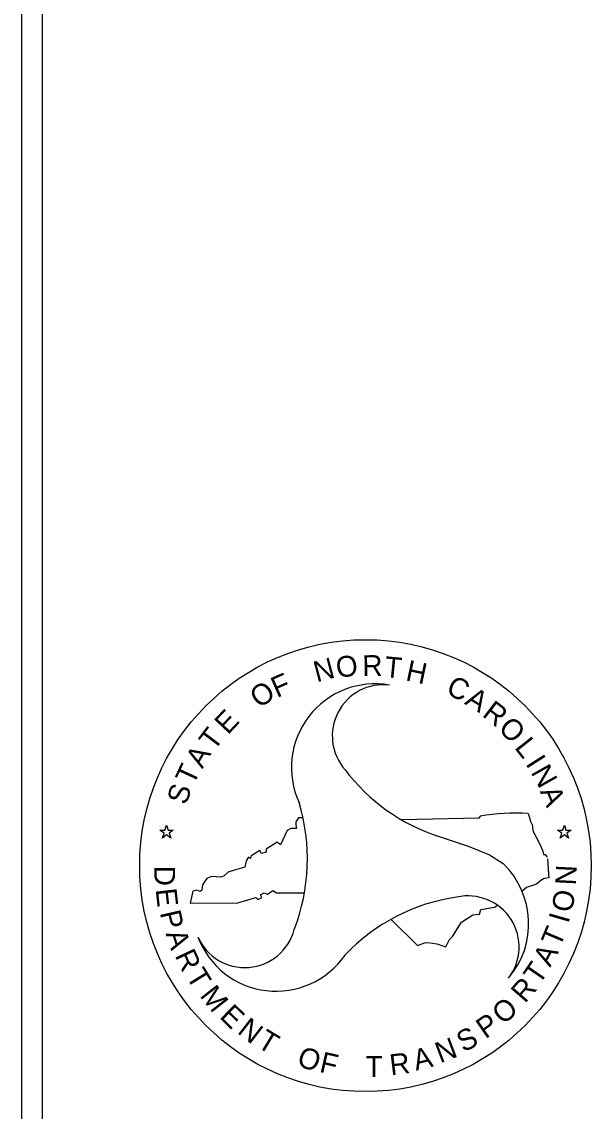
# Model space of a CAD drawing. Extents: x 2598976 to 2600165, y 728604 to 730243.
# Drawn here: x 2598980.7 to 2599099.3, y 728825.9 to 729052.5 of the extents above; entities that cross this region are included whole.
import ezdxf

# ---------------------------------------------------------------- set-up
doc = ezdxf.new("R2010")
doc.units = 0
doc.layers.add('Old_Level_63', color=7, linetype='Continuous')

msp = doc.modelspace()

# ---------------------------------------------------------------- linework, layer by layer
at = {"layer": 'Old_Level_63'}
for p, q in [((2598980.71, 728675.66), (2598980.71, 730208.07)), ((2598980.71, 728675.66), (2598980.71, 730208.07)), ((2598980.71, 728675.66), (2598980.71, 730208.07)), ((2598985.01, 728674.53), (2598985.01, 730208.54)), ((2598985.01, 728674.53), (2598985.01, 730208.54)), ((2598985.01, 728674.53), (2598985.01, 730208.54)), ((2599038.31, 728886.96), (2599037.8, 728886.13)), ((2599038.31, 728886.96), (2599037.8, 728886.13)), ((2599038.31, 728886.96), (2599037.8, 728886.13)), ((2599039.27, 728886.94), (2599038.31, 728886.96)), ((2599039.27, 728886.94), (2599038.31, 728886.96)), ((2599039.27, 728886.94), (2599038.31, 728886.96)), ((2599075.88, 728886.84), (2599059.86, 728886.48)), ((2599075.88, 728886.84), (2599059.86, 728886.48)), ((2599075.88, 728886.84), (2599059.86, 728886.48)), ((2599076.16, 728887.28), (2599075.88, 728886.84)), ((2599076.16, 728887.28), (2599075.88, 728886.84)), ((2599076.16, 728887.28), (2599075.88, 728886.84)), ((2599086.15, 728887.82), (2599086.42, 728886.98)), ((2599086.15, 728887.82), (2599086.42, 728886.98)), ((2599086.15, 728887.82), (2599086.42, 728886.98)), ((2599086.42, 728886.98), (2599086.49, 728886.62)), ((2599086.42, 728886.98), (2599086.49, 728886.62)), ((2599086.42, 728886.98), (2599086.49, 728886.62)), ((2599086.49, 728886.62), (2599086.71, 728886.05)), ((2599086.49, 728886.62), (2599086.71, 728886.05)), ((2599086.49, 728886.62), (2599086.71, 728886.05)), ((2599010.33, 728883.74), (2599009.47, 728884.37)), ((2599009.47, 728884.37), (2599010.53, 728884.37)), ((2599010.33, 728883.74), (2599009.47, 728884.37)), ((2599009.47, 728884.37), (2599010.53, 728884.37)), ((2599010.33, 728883.74), (2599009.47, 728884.37)), ((2599009.47, 728884.37), (2599010.53, 728884.37)), ((2599010.53, 728884.37), (2599010.86, 728885.38)), ((2599010.53, 728884.37), (2599010.86, 728885.38)), ((2599010.53, 728884.37), (2599010.86, 728885.38)), ((2599010.86, 728885.38), (2599011.18, 728884.37)), ((2599010.86, 728885.38), (2599011.18, 728884.37)), ((2599010.86, 728885.38), (2599011.18, 728884.37)), ((2599011.18, 728884.37), (2599012.25, 728884.37)), ((2599011.18, 728884.37), (2599012.25, 728884.37)), ((2599011.18, 728884.37), (2599012.25, 728884.37)), ((2599012.25, 728884.37), (2599011.39, 728883.74)), ((2599012.25, 728884.37), (2599011.39, 728883.74)), ((2599012.25, 728884.37), (2599011.39, 728883.74)), ((2599036.76, 728884.71), (2599035.98, 728884.31)), ((2599036.76, 728884.71), (2599035.98, 728884.31)), ((2599036.76, 728884.71), (2599035.98, 728884.31)), ((2599037.93, 728884.71), (2599036.76, 728884.71)), ((2599037.93, 728884.71), (2599036.76, 728884.71)), ((2599037.93, 728884.71), (2599036.76, 728884.71)), ((2599037.8, 728886.13), (2599037.8, 728885.48)), ((2599037.8, 728886.13), (2599037.8, 728885.48)), ((2599037.8, 728886.13), (2599037.8, 728885.48)), ((2599037.8, 728885.48), (2599037.93, 728884.71)), ((2599037.8, 728885.48), (2599037.93, 728884.71)), ((2599037.8, 728885.48), (2599037.93, 728884.71)), ((2599086.71, 728886.05), (2599087.06, 728885.34)), ((2599086.71, 728886.05), (2599087.06, 728885.34)), ((2599086.71, 728886.05), (2599087.06, 728885.34)), ((2599087.06, 728885.34), (2599087.06, 728884.84)), ((2599087.06, 728885.34), (2599087.06, 728884.84)), ((2599087.06, 728885.34), (2599087.06, 728884.84)), ((2599087.06, 728884.84), (2599087.21, 728883.99)), ((2599087.06, 728884.84), (2599087.21, 728883.99)), ((2599087.06, 728884.84), (2599087.21, 728883.99)), ((2599093.16, 728883.74), (2599092.3, 728884.37)), ((2599092.3, 728884.37), (2599093.36, 728884.37)), ((2599093.16, 728883.74), (2599092.3, 728884.37)), ((2599092.3, 728884.37), (2599093.36, 728884.37)), ((2599093.16, 728883.74), (2599092.3, 728884.37)), ((2599092.3, 728884.37), (2599093.36, 728884.37)), ((2599093.36, 728884.37), (2599093.69, 728885.38)), ((2599093.36, 728884.37), (2599093.69, 728885.38)), ((2599093.36, 728884.37), (2599093.69, 728885.38)), ((2599093.69, 728885.38), (2599094.02, 728884.37)), ((2599093.69, 728885.38), (2599094.02, 728884.37)), ((2599093.69, 728885.38), (2599094.02, 728884.37)), ((2599094.02, 728884.37), (2599095.08, 728884.37)), ((2599094.02, 728884.37), (2599095.08, 728884.37)), ((2599094.02, 728884.37), (2599095.08, 728884.37)), ((2599095.08, 728884.37), (2599094.22, 728883.74)), ((2599095.08, 728884.37), (2599094.22, 728883.74)), ((2599095.08, 728884.37), (2599094.22, 728883.74)), ((2599010, 728882.73), (2599010.33, 728883.74)), ((2599010, 728882.73), (2599010.33, 728883.74)), ((2599010, 728882.73), (2599010.33, 728883.74)), ((2599010.86, 728883.36), (2599010, 728882.73)), ((2599010.86, 728883.36), (2599010, 728882.73)), ((2599010.86, 728883.36), (2599010, 728882.73)), ((2599011.72, 728882.73), (2599010.86, 728883.36)), ((2599011.72, 728882.73), (2599010.86, 728883.36)), ((2599011.72, 728882.73), (2599010.86, 728883.36)), ((2599011.39, 728883.74), (2599011.72, 728882.73)), ((2599011.39, 728883.74), (2599011.72, 728882.73)), ((2599011.39, 728883.74), (2599011.72, 728882.73)), ((2599035.98, 728884.31), (2599034.56, 728881.33)), ((2599035.98, 728884.31), (2599034.56, 728881.33)), ((2599035.98, 728884.31), (2599034.56, 728881.33)), ((2599067.64, 728883.03), (2599073.67, 728881.04)), ((2599067.64, 728883.03), (2599073.67, 728881.04)), ((2599067.64, 728883.03), (2599073.67, 728881.04)), ((2599087.21, 728883.99), (2599087.56, 728883.48)), ((2599087.21, 728883.99), (2599087.56, 728883.48)), ((2599087.21, 728883.99), (2599087.56, 728883.48)), ((2599087.56, 728883.48), (2599087.85, 728882.92)), ((2599087.56, 728883.48), (2599087.85, 728882.92)), ((2599087.56, 728883.48), (2599087.85, 728882.92)), ((2599087.85, 728882.92), (2599088.56, 728881.42)), ((2599087.85, 728882.92), (2599088.56, 728881.42)), ((2599087.85, 728882.92), (2599088.56, 728881.42)), ((2599092.83, 728882.73), (2599093.16, 728883.74)), ((2599092.83, 728882.73), (2599093.16, 728883.74)), ((2599092.83, 728882.73), (2599093.16, 728883.74)), ((2599093.69, 728883.36), (2599092.83, 728882.73)), ((2599093.69, 728883.36), (2599092.83, 728882.73)), ((2599093.69, 728883.36), (2599092.83, 728882.73)), ((2599094.55, 728882.73), (2599093.69, 728883.36)), ((2599094.55, 728882.73), (2599093.69, 728883.36)), ((2599094.55, 728882.73), (2599093.69, 728883.36)), ((2599094.22, 728883.74), (2599094.55, 728882.73)), ((2599094.22, 728883.74), (2599094.55, 728882.73)), ((2599094.22, 728883.74), (2599094.55, 728882.73)), ((2599030.28, 728880.16), (2599028.46, 728878.99)), ((2599030.28, 728880.16), (2599028.46, 728878.99)), ((2599030.28, 728880.16), (2599028.46, 728878.99)), ((2599030.54, 728879.52), (2599030.28, 728880.16)), ((2599030.54, 728879.52), (2599030.28, 728880.16)), ((2599030.54, 728879.52), (2599030.28, 728880.16)), ((2599033.91, 728881.85), (2599031.57, 728880.42)), ((2599033.91, 728881.85), (2599031.57, 728880.42)), ((2599033.91, 728881.85), (2599031.57, 728880.42)), ((2599031.57, 728880.42), (2599031.57, 728879.77)), ((2599031.57, 728880.42), (2599031.57, 728879.77)), ((2599031.57, 728880.42), (2599031.57, 728879.77)), ((2599034.56, 728881.33), (2599033.91, 728881.85)), ((2599034.56, 728881.33), (2599033.91, 728881.85)), ((2599034.56, 728881.33), (2599033.91, 728881.85)), ((2599073.67, 728881.04), (2599078.11, 728879.23)), ((2599073.67, 728881.04), (2599078.11, 728879.23)), ((2599073.67, 728881.04), (2599078.11, 728879.23)), ((2599088.56, 728881.42), (2599089.2, 728879.99)), ((2599088.56, 728881.42), (2599089.2, 728879.99)), ((2599088.56, 728881.42), (2599089.2, 728879.99)), ((2599089.2, 728879.99), (2599089.34, 728879.28)), ((2599089.2, 728879.99), (2599089.34, 728879.28)), ((2599089.2, 728879.99), (2599089.34, 728879.28)), ((2599027.42, 728877.96), (2599027.16, 728876.66)), ((2599027.42, 728877.96), (2599027.16, 728876.66)), ((2599027.42, 728877.96), (2599027.16, 728876.66)), ((2599027.94, 728878.73), (2599027.42, 728877.96)), ((2599027.94, 728878.73), (2599027.42, 728877.96)), ((2599027.94, 728878.73), (2599027.42, 728877.96)), ((2599028.33, 728878.48), (2599027.94, 728878.73)), ((2599028.33, 728878.48), (2599027.94, 728878.73)), ((2599028.33, 728878.48), (2599027.94, 728878.73)), ((2599028.46, 728878.99), (2599028.33, 728878.48)), ((2599028.46, 728878.99), (2599028.33, 728878.48)), ((2599028.46, 728878.99), (2599028.33, 728878.48)), ((2599031.57, 728879.77), (2599030.54, 728879.52)), ((2599031.57, 728879.77), (2599030.54, 728879.52)), ((2599031.57, 728879.77), (2599030.54, 728879.52)), ((2599078.11, 728879.23), (2599080.96, 728877.4)), ((2599078.11, 728879.23), (2599080.96, 728877.4)), ((2599078.11, 728879.23), (2599080.96, 728877.4)), ((2599089.34, 728879.28), (2599089.7, 728879.28)), ((2599089.34, 728879.28), (2599089.7, 728879.28)), ((2599089.34, 728879.28), (2599089.7, 728879.28)), ((2599089.7, 728879.28), (2599090.13, 728878.78)), ((2599089.7, 728879.28), (2599090.13, 728878.78)), ((2599089.7, 728879.28), (2599090.13, 728878.78)), ((2599090.2, 728878.43), (2599090.27, 728877.29)), ((2599090.2, 728878.43), (2599090.27, 728877.29)), ((2599090.2, 728878.43), (2599090.27, 728877.29)), ((2599023.66, 728875.62), (2599022.89, 728874.84)), ((2599023.66, 728875.62), (2599022.89, 728874.84)), ((2599023.66, 728875.62), (2599022.89, 728874.84)), ((2599025.22, 728876.14), (2599023.66, 728875.62)), ((2599025.22, 728876.14), (2599023.66, 728875.62)), ((2599025.22, 728876.14), (2599023.66, 728875.62)), ((2599027.16, 728876.66), (2599025.22, 728876.14)), ((2599027.16, 728876.66), (2599025.22, 728876.14)), ((2599027.16, 728876.66), (2599025.22, 728876.14)), ((2599090.27, 728877.29), (2599090.34, 728876.36)), ((2599090.27, 728877.29), (2599090.34, 728876.36)), ((2599090.27, 728877.29), (2599090.34, 728876.36)), ((2599090.34, 728876.36), (2599090.41, 728875.22)), ((2599090.34, 728876.36), (2599090.41, 728875.22)), ((2599090.34, 728876.36), (2599090.41, 728875.22)), ((2599018.34, 728873.02), (2599018.22, 728871.86)), ((2599018.34, 728873.02), (2599018.22, 728871.86)), ((2599018.34, 728873.02), (2599018.22, 728871.86)), ((2599018.87, 728873.81), (2599018.34, 728873.02)), ((2599018.87, 728873.81), (2599018.34, 728873.02)), ((2599018.87, 728873.81), (2599018.34, 728873.02)), ((2599019.25, 728874.32), (2599018.87, 728873.81)), ((2599019.25, 728874.32), (2599018.87, 728873.81)), ((2599019.25, 728874.32), (2599018.87, 728873.81)), ((2599020.16, 728874.71), (2599019.25, 728874.32)), ((2599020.16, 728874.71), (2599019.25, 728874.32)), ((2599020.16, 728874.71), (2599019.25, 728874.32)), ((2599022.24, 728874.58), (2599020.16, 728874.71)), ((2599022.24, 728874.58), (2599020.16, 728874.71)), ((2599022.24, 728874.58), (2599020.16, 728874.71)), ((2599022.89, 728874.84), (2599022.24, 728874.58)), ((2599022.89, 728874.84), (2599022.24, 728874.58)), ((2599022.89, 728874.84), (2599022.24, 728874.58)), ((2599087.89, 728873.14), (2599085.78, 728872.43)), ((2599087.89, 728873.14), (2599085.78, 728872.43)), ((2599087.89, 728873.14), (2599085.78, 728872.43)), ((2599088.77, 728873.87), (2599087.89, 728873.14)), ((2599088.77, 728873.87), (2599087.89, 728873.14)), ((2599088.77, 728873.87), (2599087.89, 728873.14)), ((2599089.48, 728874.29), (2599088.77, 728873.87)), ((2599089.48, 728874.29), (2599088.77, 728873.87)), ((2599089.48, 728874.29), (2599088.77, 728873.87)), ((2599090.48, 728874.44), (2599089.48, 728874.29)), ((2599090.48, 728874.44), (2599089.48, 728874.29)), ((2599090.48, 728874.44), (2599089.48, 728874.29)), ((2599090.41, 728875.22), (2599090.48, 728874.44)), ((2599090.41, 728875.22), (2599090.48, 728874.44)), ((2599090.41, 728875.22), (2599090.48, 728874.44)), ((2599016.34, 728871.69), (2599015.76, 728869.21)), ((2599016.34, 728871.69), (2599015.76, 728869.21)), ((2599016.34, 728871.69), (2599015.76, 728869.21)), ((2599017.18, 728871.86), (2599016.34, 728871.69)), ((2599017.18, 728871.86), (2599016.34, 728871.69)), ((2599017.18, 728871.86), (2599016.34, 728871.69)), ((2599017.83, 728871.6), (2599017.18, 728871.86)), ((2599017.83, 728871.6), (2599017.18, 728871.86)), ((2599017.83, 728871.6), (2599017.18, 728871.86)), ((2599018.22, 728871.86), (2599017.83, 728871.6)), ((2599018.22, 728871.86), (2599017.83, 728871.6)), ((2599018.22, 728871.86), (2599017.83, 728871.6)), ((2599030.44, 728870.94), (2599031.16, 728871.36)), ((2599030.44, 728870.94), (2599031.16, 728871.36)), ((2599030.44, 728870.94), (2599031.16, 728871.36)), ((2599030.73, 728870.36), (2599030.44, 728870.94)), ((2599030.73, 728870.36), (2599030.44, 728870.94)), ((2599030.73, 728870.36), (2599030.44, 728870.94)), ((2599031.16, 728871.36), (2599031.87, 728871.08)), ((2599031.16, 728871.36), (2599031.87, 728871.08)), ((2599031.16, 728871.36), (2599031.87, 728871.08)), ((2599031.87, 728871.08), (2599033.01, 728871.79)), ((2599031.87, 728871.08), (2599033.01, 728871.79)), ((2599031.87, 728871.08), (2599033.01, 728871.79)), ((2599033.01, 728871.79), (2599033.73, 728871.36)), ((2599033.01, 728871.79), (2599033.73, 728871.36)), ((2599033.01, 728871.79), (2599033.73, 728871.36)), ((2599033.73, 728871.36), (2599039.58, 728871.36)), ((2599033.73, 728871.36), (2599039.58, 728871.36)), ((2599033.73, 728871.36), (2599039.58, 728871.36)), ((2599085.78, 728872.43), (2599084.9, 728871.65)), ((2599085.78, 728872.43), (2599084.9, 728871.65)), ((2599085.78, 728872.43), (2599084.9, 728871.65)), ((2599015.76, 728869.21), (2599025.73, 728869.22)), ((2599015.76, 728869.21), (2599025.73, 728869.22)), ((2599015.76, 728869.21), (2599025.73, 728869.22)), ((2599025.73, 728869.22), (2599029.45, 728870.36)), ((2599025.73, 728869.22), (2599029.45, 728870.36)), ((2599025.73, 728869.22), (2599029.45, 728870.36)), ((2599029.45, 728870.36), (2599029.87, 728869.93)), ((2599029.45, 728870.36), (2599029.87, 728869.93)), ((2599029.45, 728870.36), (2599029.87, 728869.93)), ((2599029.87, 728869.93), (2599030.73, 728870.36)), ((2599029.87, 728869.93), (2599030.73, 728870.36)), ((2599029.87, 728869.93), (2599030.73, 728870.36)), ((2599079.12, 728868.31), (2599079.8, 728868.73)), ((2599079.12, 728868.31), (2599079.8, 728868.73)), ((2599079.12, 728868.31), (2599079.8, 728868.73)), ((2599072.29, 728865.21), (2599074.62, 728866.76)), ((2599072.29, 728865.21), (2599074.62, 728866.76)), ((2599072.29, 728865.21), (2599074.62, 728866.76)), ((2599074.62, 728866.76), (2599076.02, 728866.92)), ((2599074.62, 728866.76), (2599076.02, 728866.92)), ((2599074.62, 728866.76), (2599076.02, 728866.92)), ((2599076.02, 728866.92), (2599076.32, 728867.85)), ((2599076.02, 728866.92), (2599076.32, 728867.85)), ((2599076.02, 728866.92), (2599076.32, 728867.85)), ((2599076.32, 728867.85), (2599079.12, 728868.31)), ((2599076.32, 728867.85), (2599079.12, 728868.31)), ((2599076.32, 728867.85), (2599079.12, 728868.31)), ((2599057.61, 728865.8), (2599063.14, 728860.4)), ((2599057.61, 728865.8), (2599063.14, 728860.4)), ((2599057.61, 728865.8), (2599063.14, 728860.4)), ((2599070.43, 728862.26), (2599072.29, 728865.21)), ((2599070.43, 728862.26), (2599072.29, 728865.21)), ((2599070.43, 728862.26), (2599072.29, 728865.21)), ((2599069.81, 728861.64), (2599070.43, 728862.26)), ((2599069.81, 728861.64), (2599070.43, 728862.26)), ((2599069.81, 728861.64), (2599070.43, 728862.26)), ((2599063.14, 728860.4), (2599064.59, 728860.95)), ((2599063.14, 728860.4), (2599064.59, 728860.95)), ((2599063.14, 728860.4), (2599064.59, 728860.95)), ((2599064.59, 728860.95), (2599065.32, 728861.02)), ((2599064.59, 728860.95), (2599065.32, 728861.02)), ((2599064.59, 728860.95), (2599065.32, 728861.02)), ((2599065.32, 728861.02), (2599067.17, 728860.71)), ((2599065.32, 728861.02), (2599067.17, 728860.71)), ((2599065.32, 728861.02), (2599067.17, 728860.71)), ((2599067.17, 728860.71), (2599069.03, 728860.09)), ((2599067.17, 728860.71), (2599069.03, 728860.09)), ((2599067.17, 728860.71), (2599069.03, 728860.09)), ((2599069.03, 728860.09), (2599069.81, 728861.64)), ((2599069.03, 728860.09), (2599069.81, 728861.64)), ((2599069.03, 728860.09), (2599069.81, 728861.64))]:
    msp.add_line(p, q, dxfattribs=at)
msp.add_ellipse((2599052.28, 728876.98), major_axis=(0, 47.01), ratio=0.999998, dxfattribs=at)
msp.add_ellipse((2599052.28, 728876.98), major_axis=(0, 47.01), ratio=0.999998, dxfattribs=at)
msp.add_ellipse((2599052.28, 728876.98), major_axis=(0, 47.01), ratio=0.999998, dxfattribs=at)
for centre, major_axis, start_param, end_param in [((2599054.27, 728897.4), (0, 17.41), 6.109058, 8.2851), ((2599054.27, 728897.4), (0, 17.41), 6.109058, 8.2851), ((2599054.27, 728897.4), (0, 17.41), 6.109058, 8.2851), ((2599056.01, 728903.98), (0, 10.64), 6.162847, 8.577667), ((2599056.01, 728903.98), (0, 10.64), 6.162847, 8.577667), ((2599056.01, 728903.98), (0, 10.64), 6.162847, 8.577667), ((2599079.8, 728920.98), (0, 39.85), 2.218819, 2.83155), ((2599079.8, 728920.98), (0, 39.85), 2.218819, 2.83155), ((2599079.8, 728920.98), (0, 39.85), 2.218819, 2.83155), ((2598999.52, 728878.38), (0, 40.67), 4.343009, 5.005456), ((2598999.52, 728878.38), (0, 40.67), 4.343009, 5.005456), ((2598999.52, 728878.38), (0, 40.67), 4.343009, 5.005456), ((2599083.53, 728843.75), (0, 44.15), 6.223932, 6.450896), ((2599083.53, 728843.75), (0, 44.15), 6.223932, 6.450896), ((2599083.53, 728843.75), (0, 44.15), 6.223932, 6.450896), ((2599068.85, 728864.89), (0, 17.41), 4.005429, 5.514388), ((2599068.85, 728864.89), (0, 17.41), 4.005429, 5.514388), ((2599068.85, 728864.89), (0, 17.41), 4.005429, 5.514388), ((2599073.64, 728860.05), (0, 10.64), 4.059218, 6.501464), ((2599073.64, 728860.05), (0, 10.64), 4.059218, 6.501464), ((2599073.64, 728860.05), (0, 10.64), 4.059218, 6.501464), ((2599077.08, 728830.77), (0, 40.09), 0.143919, 0.810937), ((2599077.08, 728830.77), (0, 40.09), 0.143919, 0.810937), ((2599077.08, 728830.77), (0, 40.09), 0.143919, 0.810937), ((2599027.15, 728866.41), (0, 10.64), 1.985995, 4.454419), ((2599027.15, 728866.41), (0, 10.64), 1.985995, 4.454419), ((2599027.15, 728866.41), (0, 10.64), 1.985995, 4.454419), ((2599033.69, 728868.27), (0, 17.41), 1.932206, 4.108248), ((2599033.69, 728868.27), (0, 17.41), 1.932206, 4.108248), ((2599033.69, 728868.27), (0, 17.41), 1.932206, 4.108248)]:
    msp.add_ellipse(centre, major_axis=major_axis, ratio=0.999998, start_param=start_param, end_param=end_param, dxfattribs=at)

# ---------------------------------------------------------------- texts
for s, rotation, p in [('O', 8.4638, (2599046.47, 728915.99)), ('O', 8.4638, (2599046.47, 728915.99)), ('O', 8.4638, (2599046.47, 728915.99)), ('R', 0.8867, (2599051.66, 728916.41)), ('R', 0.8867, (2599051.66, 728916.41)), ('R', 0.8867, (2599051.66, 728916.41)), ('N', 14.8924, (2599042.14, 728915.1)), ('N', 14.8924, (2599042.14, 728915.1)), ('N', 14.8924, (2599042.14, 728915.1)), ('T', 354.4581, (2599056.08, 728916.24)), ('T', 354.4581, (2599056.08, 728916.24)), ('T', 354.4581, (2599056.08, 728916.24)), ('H', 348.0295, (2599060.46, 728915.56)), ('H', 348.0295, (2599060.46, 728915.56)), ('H', 348.0295, (2599060.46, 728915.56)), ('F', 23.9, (2599033.85, 728911.82)), ('F', 23.9, (2599033.85, 728911.82)), ('F', 23.9, (2599033.85, 728911.82)), ('C', 335.1724, (2599068.84, 728912.78)), ('C', 335.1724, (2599068.84, 728912.78)), ('C', 335.1724, (2599068.84, 728912.78)), ('O', 34.1673, (2599030.12, 728909.61)), ('O', 34.1673, (2599030.12, 728909.61)), ('O', 34.1673, (2599030.12, 728909.61)), ('A', 328.7438, (2599072.74, 728910.7)), ('A', 328.7438, (2599072.74, 728910.7)), ('A', 328.7438, (2599072.74, 728910.7)), ('E', 46.6097, (2599023.61, 728904.07)), ('E', 46.6097, (2599023.61, 728904.07)), ('E', 46.6097, (2599023.61, 728904.07)), ('R', 322.3152, (2599076.39, 728908.19)), ('R', 322.3152, (2599076.39, 728908.19)), ('R', 322.3152, (2599076.39, 728908.19)), ('O', 315.8866, (2599079.73, 728905.29)), ('O', 315.8866, (2599079.73, 728905.29)), ('O', 315.8866, (2599079.73, 728905.29)), ('T', 53.0383, (2599020.76, 728900.69)), ('T', 53.0383, (2599020.76, 728900.69)), ('T', 53.0383, (2599020.76, 728900.69)), ('L', 308.4531, (2599083.17, 728901.51)), ('L', 308.4531, (2599083.17, 728901.51)), ('L', 308.4531, (2599083.17, 728901.51)), ('A', 59.4668, (2599018.3, 728897.02)), ('A', 59.4668, (2599018.3, 728897.02)), ('A', 59.4668, (2599018.3, 728897.02)), ('T', 65.1724, (2599016.48, 728893.54)), ('T', 65.1724, (2599016.48, 728893.54)), ('T', 65.1724, (2599016.48, 728893.54)), ('I', 302.5518, (2599085.52, 728898.2)), ('I', 302.5518, (2599085.52, 728898.2)), ('I', 302.5518, (2599085.52, 728898.2)), ('N', 299.4957, (2599086.61, 728896.4)), ('N', 299.4957, (2599086.61, 728896.4)), ('N', 299.4957, (2599086.61, 728896.4)), ('S', 72.8029, (2599015, 728889.45)), ('S', 72.8029, (2599015, 728889.45)), ('S', 72.8029, (2599015, 728889.45)), ('A', 293.0671, (2599088.57, 728892.43)), ('A', 293.0671, (2599088.57, 728892.43)), ('A', 293.0671, (2599088.57, 728892.43)), ('D', 270, (2599008.31, 728876.95)), ('D', 270, (2599008.31, 728876.95)), ('D', 270, (2599008.31, 728876.95)), ('N', 87.1482, (2599096.1, 728872.83)), ('N', 87.1482, (2599096.1, 728872.83)), ('N', 87.1482, (2599096.1, 728872.83)), ('E', 276.4286, (2599008.58, 728872.05)), ('E', 276.4286, (2599008.58, 728872.05)), ('E', 276.4286, (2599008.58, 728872.05)), ('O', 80.8284, (2599095.3, 728867.12)), ('O', 80.8284, (2599095.3, 728867.12)), ('O', 80.8284, (2599095.3, 728867.12)), ('P', 282.8571, (2599009.44, 728867.2)), ('P', 282.8571, (2599009.44, 728867.2)), ('P', 282.8571, (2599009.44, 728867.2)), ('I', 73.9053, (2599094.51, 728864.81)), ('I', 73.9053, (2599094.51, 728864.81)), ('I', 73.9053, (2599094.51, 728864.81)), ('T', 66.9823, (2599092.73, 728859.81)), ('T', 66.9823, (2599092.73, 728859.81)), ('T', 66.9823, (2599092.73, 728859.81)), ('A', 288.6919, (2599010.63, 728862.84)), ('A', 288.6919, (2599010.63, 728862.84)), ('A', 288.6919, (2599010.63, 728862.84)), ('R', 295.1204, (2599012.52, 728858.31)), ('R', 295.1204, (2599012.52, 728858.31)), ('R', 295.1204, (2599012.52, 728858.31)), ('A', 61.0261, (2599090.73, 728855.71)), ('A', 61.0261, (2599090.73, 728855.71)), ('A', 61.0261, (2599090.73, 728855.71)), ('T', 55.3847, (2599088.46, 728852.03)), ('T', 55.3847, (2599088.46, 728852.03)), ('T', 55.3847, (2599088.46, 728852.03)), ('T', 301.549, (2599014.83, 728853.96)), ('T', 301.549, (2599014.83, 728853.96)), ('T', 301.549, (2599014.83, 728853.96)), ('R', 49.0467, (2599085.48, 728848.19)), ('R', 49.0467, (2599085.48, 728848.19)), ('R', 49.0467, (2599085.48, 728848.19)), ('M', 307.9776, (2599017.65, 728849.91)), ('M', 307.9776, (2599017.65, 728849.91)), ('M', 307.9776, (2599017.65, 728849.91)), ('E', 315.8505, (2599021.7, 728845.43)), ('E', 315.8505, (2599021.7, 728845.43)), ('E', 315.8505, (2599021.7, 728845.43)), ('O', 40.7624, (2599080.97, 728843.74)), ('O', 40.7624, (2599080.97, 728843.74)), ('O', 40.7624, (2599080.97, 728843.74)), ('P', 34.6154, (2599077.26, 728840.82)), ('P', 34.6154, (2599077.26, 728840.82)), ('P', 34.6154, (2599077.26, 728840.82)), ('N', 322.2791, (2599025.41, 728842.24)), ('N', 322.2791, (2599025.41, 728842.24)), ('N', 322.2791, (2599025.41, 728842.24)), ('T', 328.7077, (2599029.47, 728839.41)), ('T', 328.7077, (2599029.47, 728839.41)), ('T', 328.7077, (2599029.47, 728839.41)), ('S', 27.6923, (2599072.7, 728838.06)), ('S', 27.6923, (2599072.7, 728838.06)), ('S', 27.6923, (2599072.7, 728838.06)), ('O', 340.7143, (2599037.78, 728835.46)), ('O', 340.7143, (2599037.78, 728835.46)), ('O', 340.7143, (2599037.78, 728835.46)), ('A', 13.8462, (2599062.8, 728834.31)), ('A', 13.8462, (2599062.8, 728834.31)), ('A', 13.8462, (2599062.8, 728834.31)), ('N', 20.7693, (2599067.82, 728835.84)), ('N', 20.7693, (2599067.82, 728835.84)), ('N', 20.7693, (2599067.82, 728835.84)), ('F', 347.1428, (2599042.51, 728834.09)), ('F', 347.1428, (2599042.51, 728834.09)), ('F', 347.1428, (2599042.51, 728834.09)), ('R', 6.9231, (2599057.57, 728833.36)), ('R', 6.9231, (2599057.57, 728833.36)), ('R', 6.9231, (2599057.57, 728833.36))]:
    msp.add_text(s, height=4.34, rotation=rotation, dxfattribs=at).set_placement(p)
msp.add_text('T', height=4.34, dxfattribs=at).set_placement((2599052.3, 728833.03))
msp.add_text('T', height=4.34, dxfattribs=at).set_placement((2599052.3, 728833.03))
msp.add_text('T', height=4.34, dxfattribs=at).set_placement((2599052.3, 728833.03))

doc.saveas('drawing.dxf')
